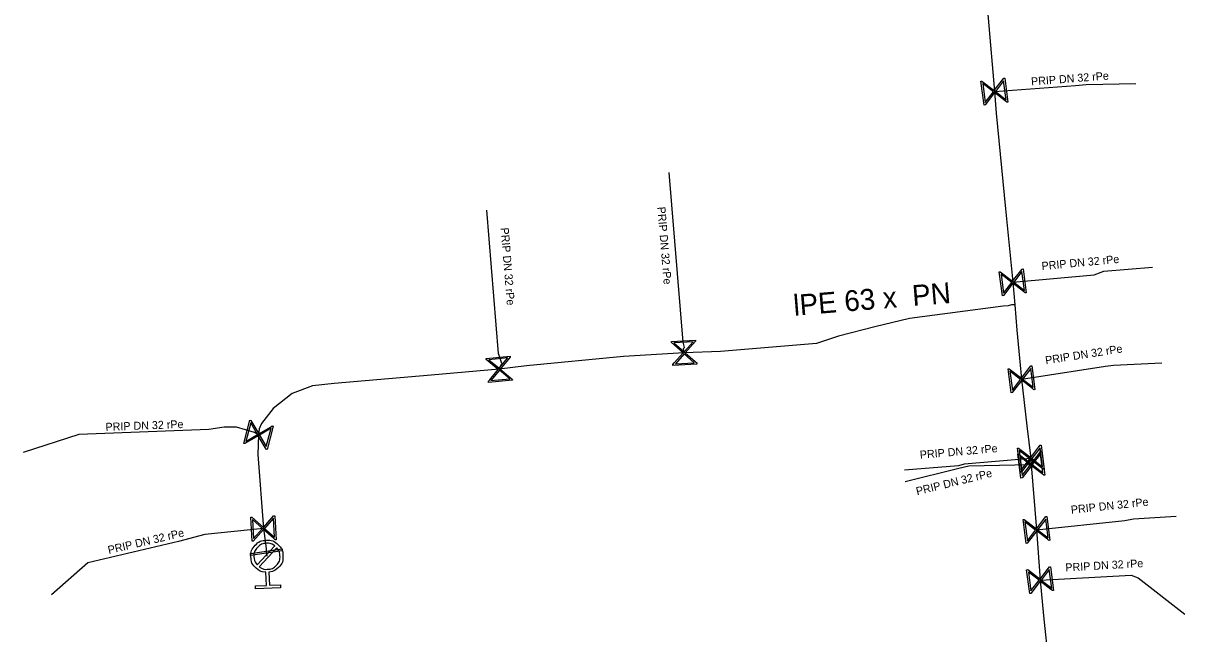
# Model space of a CAD drawing. Extents: x -643842 to -636370, y -1119190 to -1110210.
# Drawn here: x -641063.2 to -640990.7, y -1114645.4 to -1114607.2 of the extents above; entities that cross this region are included whole.
import ezdxf

# ---------------------------------------------------------------- set-up
doc = ezdxf.new("R2010")
doc.units = 0
for name, color, linetype in [('22', 7, 'Continuous'), ('Default', 7, 'Continuous'), ('Level 16', 7, 'Continuous'), ('Level 20', 7, 'Continuous'), ('Level 21', 7, 'Continuous'), ('Level 23', 7, 'Continuous'), ('Level 33', 7, 'Continuous')]:
    doc.layers.add(name, color=color, linetype=linetype)

msp = doc.modelspace()

# ---------------------------------------------------------------- linework, layer by layer
at = {"layer": 'Default'}
for points in [[(-641048.061, -1114641.518), (-641048.421, -1114641.5), (-641048.686, -1114641.249), (-641048.987, -1114640.965), (-641049, -1114640.549), (-641049.013, -1114640.135), (-641048.729, -1114639.834), (-641048.445, -1114639.533), (-641048.029, -1114639.52), (-641047.617, -1114639.508), (-641047.315, -1114639.79), (-641047.014, -1114640.073), (-641047.001, -1114640.487), (-641046.988, -1114640.903), (-641047.269, -1114641.204), (-641047.519, -1114641.474), (-641047.877, -1114641.513)], [(-641047.512, -1114639.868), (-641047.735, -1114639.701), (-641048.023, -1114639.71), (-641048.359, -1114639.72), (-641048.59, -1114639.965), (-641048.821, -1114640.21), (-641048.81, -1114640.547), (-641048.801, -1114640.836), (-641048.621, -1114641.047)], [(-641048.488, -1114641.172), (-641048.265, -1114641.343), (-641047.973, -1114641.334), (-641047.635, -1114641.323), (-641047.405, -1114641.079), (-641047.175, -1114640.834), (-641047.186, -1114640.496), (-641047.195, -1114640.204), (-641047.379, -1114639.993)]]:
    msp.add_open_spline(points, degree=3, dxfattribs=at)
at = {"layer": 'Level 16'}
for points in [[(-641001.917, -1114610.657), (-641001.725, -1114612.145), (-641001.79, -1114612.153), (-641001.89, -1114612.071), (-641002.555, -1114611.559), (-641003.147, -1114612.328), (-641003.213, -1114612.337), (-641003.405, -1114610.849), (-641003.34, -1114610.841), (-641002.571, -1114611.436), (-641002.059, -1114610.77), (-641001.983, -1114610.666), (-641001.917, -1114610.657)], [(-641001.99, -1114610.825), (-641002.502, -1114611.49), (-641001.838, -1114612), (-641001.99, -1114610.825)], [(-641003.139, -1114612.174), (-641002.625, -1114611.506), (-641003.292, -1114610.993), (-641003.139, -1114612.174)], [(-641000.772, -1114622.567), (-641000.58, -1114624.055), (-641000.645, -1114624.063), (-641000.745, -1114623.981), (-641001.41, -1114623.469), (-641002.002, -1114624.238), (-641002.068, -1114624.247), (-641002.26, -1114622.759), (-641002.195, -1114622.751), (-641001.426, -1114623.346), (-641000.914, -1114622.68), (-641000.838, -1114622.576), (-641000.772, -1114622.567)], [(-641001.994, -1114624.084), (-641001.48, -1114623.416), (-641002.147, -1114622.903), (-641001.994, -1114624.084)], [(-641000.845, -1114622.735), (-641001.357, -1114623.4), (-641000.693, -1114623.91), (-641000.845, -1114622.735)], [(-641021.145, -1114628.513), (-641022.643, -1114628.605), (-641022.647, -1114628.539), (-641022.558, -1114628.445), (-641022.003, -1114627.815), (-641022.731, -1114627.173), (-641022.735, -1114627.107), (-641021.237, -1114627.015), (-641021.233, -1114627.081), (-641021.879, -1114627.808), (-641021.248, -1114628.363), (-641021.149, -1114628.447), (-641021.145, -1114628.513)], [(-641022.577, -1114627.192), (-641021.944, -1114627.749), (-641021.388, -1114627.119), (-641022.577, -1114627.192)], [(-641032.673, -1114629.517), (-641034.167, -1114629.657), (-641034.173, -1114629.591), (-641034.088, -1114629.495), (-641033.553, -1114628.847), (-641034.3, -1114628.229), (-641034.307, -1114628.163), (-641032.813, -1114628.023), (-641032.807, -1114628.089), (-641033.429, -1114628.836), (-641032.781, -1114629.371), (-641032.68, -1114629.451), (-641032.673, -1114629.517)], [(-641034.146, -1114628.242), (-641033.496, -1114628.78), (-641032.96, -1114628.131), (-641034.146, -1114628.242)], [(-641021.308, -1114628.429), (-641021.937, -1114627.874), (-641022.49, -1114628.501), (-641021.308, -1114628.429)], [(-641032.839, -1114629.438), (-641033.485, -1114628.904), (-641034.018, -1114629.548), (-641032.839, -1114629.438)], [(-641000.222, -1114628.62), (-641000.03, -1114630.108), (-641000.095, -1114630.116), (-641000.195, -1114630.034), (-641000.86, -1114629.522), (-641001.452, -1114630.291), (-641001.518, -1114630.3), (-641001.71, -1114628.812), (-641001.645, -1114628.804), (-641000.876, -1114629.399), (-641000.364, -1114628.733), (-641000.288, -1114628.629), (-641000.222, -1114628.62)], [(-641001.444, -1114630.137), (-641000.93, -1114629.469), (-641001.597, -1114628.956), (-641001.444, -1114630.137)], [(-641000.295, -1114628.788), (-641000.807, -1114629.453), (-641000.143, -1114629.963), (-641000.295, -1114628.788)], [(-641047.615, -1114632.394), (-641047.994, -1114633.845), (-641048.058, -1114633.829), (-641048.119, -1114633.716), (-641048.545, -1114632.991), (-641049.382, -1114633.483), (-641049.445, -1114633.466), (-641049.066, -1114632.015), (-641049.002, -1114632.031), (-641048.513, -1114632.871), (-641047.789, -1114632.445), (-641047.678, -1114632.377), (-641047.615, -1114632.394)], [(-641049.316, -1114633.342), (-641048.589, -1114632.915), (-641049.015, -1114632.19), (-641049.316, -1114633.342)], [(-641047.745, -1114632.523), (-641048.469, -1114632.947), (-641048.045, -1114633.669), (-641047.745, -1114632.523)], [(-640999.642, -1114633.58), (-640999.45, -1114635.068), (-640999.515, -1114635.076), (-640999.615, -1114634.994), (-641000.28, -1114634.482), (-641000.872, -1114635.251), (-641000.938, -1114635.26), (-641001.13, -1114633.772), (-641001.065, -1114633.764), (-641000.296, -1114634.359), (-640999.784, -1114633.693), (-640999.708, -1114633.589), (-640999.642, -1114633.58)], [(-640999.611, -1114633.958), (-640999.419, -1114635.446), (-640999.484, -1114635.454), (-640999.584, -1114635.372), (-641000.249, -1114634.86), (-641000.841, -1114635.629), (-641000.907, -1114635.638), (-641001.099, -1114634.15), (-641001.034, -1114634.142), (-641000.265, -1114634.737), (-640999.753, -1114634.071), (-640999.677, -1114633.967), (-640999.611, -1114633.958)], [(-641000.864, -1114635.097), (-641000.35, -1114634.429), (-641001.017, -1114633.916), (-641000.864, -1114635.097)], [(-640999.715, -1114633.748), (-641000.227, -1114634.413), (-640999.563, -1114634.923), (-640999.715, -1114633.748)], [(-640999.684, -1114634.126), (-641000.196, -1114634.791), (-640999.532, -1114635.301), (-640999.684, -1114634.126)], [(-641000.833, -1114635.475), (-641000.319, -1114634.807), (-641000.986, -1114634.294), (-641000.833, -1114635.475)], [(-641047.517, -1114637.985), (-641047.425, -1114639.483), (-641047.491, -1114639.487), (-641047.585, -1114639.398), (-641048.215, -1114638.843), (-641048.857, -1114639.571), (-641048.923, -1114639.575), (-641049.015, -1114638.077), (-641048.949, -1114638.073), (-641048.222, -1114638.719), (-641047.667, -1114638.088), (-641047.583, -1114637.989), (-641047.517, -1114637.985)], [(-641048.838, -1114639.417), (-641048.281, -1114638.784), (-641048.911, -1114638.228), (-641048.838, -1114639.417)], [(-641047.601, -1114638.148), (-641048.156, -1114638.777), (-641047.529, -1114639.33), (-641047.601, -1114638.148)], [(-640999.286, -1114638.031), (-640999.094, -1114639.519), (-640999.159, -1114639.527), (-640999.259, -1114639.445), (-640999.924, -1114638.933), (-641000.516, -1114639.702), (-641000.582, -1114639.711), (-641000.774, -1114638.223), (-641000.709, -1114638.215), (-640999.94, -1114638.81), (-640999.428, -1114638.144), (-640999.352, -1114638.04), (-640999.286, -1114638.031)], [(-641000.508, -1114639.548), (-640999.994, -1114638.88), (-641000.661, -1114638.367), (-641000.508, -1114639.548)], [(-640999.359, -1114638.199), (-640999.871, -1114638.864), (-640999.207, -1114639.374), (-640999.359, -1114638.199)], [(-641047.042, -1114640.185), (-641049.02, -1114640.478), (-641049.038, -1114640.355), (-641047.06, -1114640.062), (-641047.042, -1114640.185)], [(-640999.062, -1114641.17), (-640998.87, -1114642.658), (-640998.935, -1114642.666), (-640999.035, -1114642.584), (-640999.7, -1114642.072), (-641000.292, -1114642.841), (-641000.358, -1114642.85), (-641000.55, -1114641.362), (-641000.485, -1114641.354), (-640999.716, -1114641.949), (-640999.204, -1114641.283), (-640999.128, -1114641.179), (-640999.062, -1114641.17)], [(-640999.135, -1114641.338), (-640999.647, -1114642.003), (-640998.983, -1114642.513), (-640999.135, -1114641.338)], [(-641000.284, -1114642.687), (-640999.77, -1114642.019), (-641000.437, -1114641.506), (-641000.284, -1114642.687)]]:
    msp.add_lwpolyline(points, dxfattribs=at)
at = {"layer": 'Level 21'}
for points in [[(-641005.53, -1114577.9), (-641005.1, -1114582.42), (-641005.01, -1114583.15), (-641004.63, -1114588.03), (-641004.52, -1114589.09), (-641004.167, -1114593.648), (-641004.06, -1114595.03), (-641003.666, -1114599.532), (-641003.53, -1114600.96), (-641003.048, -1114605.985), (-641002.96, -1114606.91), (-641002.565, -1114611.497), (-641002.45, -1114612.84), (-641001.88, -1114618.81), (-641001.42, -1114623.407), (-641001.28, -1114624.81)], [(-641001.28, -1114624.81), (-641001.49, -1114624.81), (-641001.71, -1114624.87), (-641002.01, -1114624.9), (-641007.87, -1114625.66), (-641010.03, -1114626.18), (-641012.3, -1114626.77), (-641013.68, -1114627.23), (-641019.67, -1114627.72), (-641021.94, -1114627.81), (-641025.74, -1114628.04), (-641031.78, -1114628.62), (-641033.49, -1114628.84), (-641037.751, -1114629.208), (-641043.8, -1114629.73), (-641045.16, -1114629.87), (-641046.43, -1114630.35), (-641047.62, -1114631.29), (-641048.35, -1114632.22), (-641048.49, -1114632.55), (-641048.53, -1114632.93), (-641048.56, -1114634.17), (-641048.22, -1114638.78), (-641048.05, -1114640.03), (-641048.04, -1114640.27), (-641048, -1114640.52)], [(-641001.28, -1114624.81), (-641001.17, -1114626.4), (-641000.87, -1114629.46), (-641000.53, -1114632.366), (-641000.29, -1114634.42), (-641000.259, -1114634.798), (-640999.934, -1114638.871), (-640999.71, -1114642.01), (-640999.49, -1114644.23), (-640999.19, -1114647.2)]]:
    msp.add_lwpolyline(points, dxfattribs=at)
at = {"layer": 'Level 23'}
for points in [[(-641002.565, -1114611.497), (-640997.49, -1114611.11), (-640996.84, -1114611.05), (-640993.73, -1114610.994)], [(-641021.94, -1114627.81), (-641021.98, -1114627.55), (-641021.93, -1114627.47), (-641022, -1114627.15), (-641022.876, -1114616.558)], [(-641033.49, -1114628.84), (-641033.32, -1114628.48), (-641033.54, -1114627.85), (-641034.269, -1114618.892)], [(-641001.42, -1114623.407), (-640996.34, -1114622.94), (-640995.73, -1114622.72), (-640992.688, -1114622.463)], [(-641000.87, -1114629.46), (-640995.62, -1114628.64), (-640995.13, -1114628.59), (-640992.101, -1114628.437)], [(-641048.53, -1114632.93), (-641048.77, -1114632.79), (-641049.9, -1114632.45), (-641050.68, -1114632.46), (-641051.64, -1114632.61), (-641059.76, -1114632.91), (-641063.223, -1114634.03)], [(-641000.29, -1114634.42), (-641004.46, -1114634.77), (-641004.81, -1114634.86), (-641008.188, -1114635.149)], [(-641000.259, -1114634.798), (-641000.34, -1114634.8), (-641004.17, -1114634.9), (-641004.78, -1114635.03), (-641008.146, -1114635.864)], [(-640999.934, -1114638.871), (-640994.41, -1114638.29), (-640993.87, -1114638.17), (-640991.207, -1114638.019)], [(-641048.22, -1114638.78), (-641051.89, -1114639.15), (-641053.53, -1114639.59), (-641059.19, -1114640.92), (-641061.462, -1114642.923)], [(-640999.71, -1114642.01), (-640994.03, -1114641.69), (-640993.58, -1114641.87), (-640990.675, -1114644.127)]]:
    msp.add_lwpolyline(points, dxfattribs=at)
at = {"layer": 'Level 33'}
for points in [[(-641048.621, -1114641.047), (-641047.512, -1114639.868)], [(-641047.379, -1114639.993), (-641048.488, -1114641.172)], [(-641047.877, -1114641.513), (-641047.851, -1114642.333), (-641047.162, -1114642.311), (-641047.157, -1114642.495), (-641048.718, -1114642.543), (-641048.724, -1114642.36), (-641048.035, -1114642.338), (-641048.061, -1114641.518)]]:
    msp.add_lwpolyline(points, dxfattribs=at)

# ---------------------------------------------------------------- texts
at = {"layer": '22'}
for rotation, p in [(4.36072, (-641000.256, -1114611.113)), (274.72783, (-641023.617, -1114618.708)), (274.65246, (-641033.403, -1114620.011)), (5.25239, (-640999.595, -1114622.638)), (8.87733, (-640999.35, -1114628.532)), (2.11588, (-641058.073, -1114632.688)), (4.88995, (-641007.202, -1114634.429)), (13.91603, (-641007.392, -1114636.712)), (6.00415, (-640997.762, -1114637.862)), (13.22359, (-641057.875, -1114640.381)), (3.22452, (-640998.117, -1114641.469))]:
    msp.add_text('PRIP DN 32 rPe', height=0.5, rotation=rotation, dxfattribs=at).set_placement(p)
at = {"layer": 'Level 20'}
msp.add_text('lPE 63 x  PN ', height=1.3, rotation=4.67655, dxfattribs=at).set_placement((-641015.067, -1114625.498))

doc.saveas('drawing.dxf')
